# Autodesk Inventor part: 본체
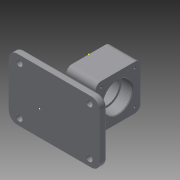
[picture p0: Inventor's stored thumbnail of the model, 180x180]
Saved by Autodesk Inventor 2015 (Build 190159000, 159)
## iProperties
Created: 2020-11
Part Number: 본체
Material: 일반
Document SubType Name: Modeling
Designer: pc-04
Density: 1 g/cm^3
Appearance: 기본값
Author: pc-04
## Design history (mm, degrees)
sketch "스케치2"
  geometry: L1 (-32, 32)-(32, 32); L2 (32, 32)-(32, -32); L3 (32, -32)-(-32, -32); L4 (-32, -32)-(-32, 32); L5 (0, 7.175)-(0, -7.867) reference; L6 (9.729, 0)-(-7.281, 0) reference; 1 further point
  constraints: 12 end point, 3 horizontal, 2 parallel, 2 vertical, 1 perpendicular, 3 other
  dimensions: "d0" = 64 distance of L1.end L2.end; "d1" = 64 distance of L2.end L3.end; "d2" = 32 distance between parallel lines of L3 L6; "d3" = 32 distance between parallel lines of L4 L5
extrude "돌출1" new body sketch "스케치2" distance "d4" = 42; taper "d5" = 0 deg
sketch "스케치5"
  geometry: 1 further point
sketch "스케치6"
  geometry: C1 r 21 at (0, 0); 1 further point
  constraints: 1 centre point, 1 coincident
  dimensions: "d17" = 42 diameter of C1
extrude "돌출3" cut sketch "스케치6" distance "d18" = 16; taper "d19" = 0 deg
sketch "스케치7"
  geometry: C1 r 21 at (0, 0); 1 further point
  constraints: 1 centre point, 1 coincident
  dimensions: "d20" = 42 diameter of C1
extrude "돌출4" cut sketch "스케치7" distance "d21" = 16; taper "d22" = 0 deg
sketch "스케치8"
  geometry: 1 further point
sketch "스케치9"
  geometry: C1 r 18 at (0, 0); 1 further point
  constraints: 1 centre point, 1 coincident
  dimensions: "d23" = 36 diameter of C1
extrude "돌출5" cut sketch "스케치9" distance "d24" = 16; taper "d25" = 0 deg
sketch "스케치10"
  geometry: 4 further points
hole "구멍1" sketch "스케치10" at (-24, 24), (-24, -24), (24, -24), (24, 24) diameter "d31" = 3.242; stored, may be unused: countersink angle "d35" = 90 deg, drill point angle "d37" = 118 deg; dims "d32" = 8, "d33" = 4, "d34" = 2, "d36" = 10
sketch "스케치11"
  geometry: L1 (0, 42.923)-(0, -48.07); L2 (-61.306, 0)-(57.445, 0); L3 (24, 42.923)-(24, -48.07); L4 (-24, 42.923)-(-24, -48.07); L5 (-61.306, 24)-(57.445, 24); L6 (-61.306, -24)-(57.445, -24); 5 further points
  constraints: 12 end point, 8 point on line, 4 parallel, 1 horizontal, 1 vertical
  dimensions: "d38" = 24 distance between parallel lines of L1 L3; "d39" = 24 distance between parallel lines of L1 L4; "d40" = 24 distance between parallel lines of L2 L5; "d41" = 24 distance between parallel lines of L2 L6
hole "구멍2" sketch "스케치11" at (-24, 24), (-24, -24), (24, -24), (24, 24) diameter "d42" = 3.242; stored, may be unused: countersink angle "d46" = 90 deg, drill point angle "d48" = 118 deg; dims "d43" = 8, "d44" = 4, "d45" = 2, "d47" = 10
node "작업 평면2"
sketch "스케치14"
  geometry: 1 further point
sketch "스케치15"
  geometry: 1 further point
sketch "스케치16" dims "d24" = 16
  geometry: L1 (-42, -32)-(0, -32); L2 (44, 52)-(-86, 52); L3 (-86, 52)-(-86, -36); L4 (-86, -36)-(44, -36); L5 (44, -36)-(44, 52); L6 (0, -33.785)-(0, 34.387); L7 (0, 32)-(0, -32) reference; L8 (-21, -33.785)-(-21, 34.387)
  constraints: 14 end point, 3 parallel, 1 collinear, 1 horizontal, 1 perpendicular, 1 other
  dimensions: "d78" = 130 distance of L2.start L2.end; "d79" = 88 distance of L2.end L3.end; "d201" = 21 distance between parallel lines of L6 L8; "d202" = 65 distance between parallel lines of L5 L8
extrude "돌출8" join sketch "스케치16" distance "d84" = 10; taper "d85" = 0 deg
sketch "스케치19"
  geometry: L1 (0, -32)-(42, -32); L2 (42, 32)-(0, 32); L3 (47.791, -32)-(-18.485, -32); L4 (86, 36)-(-44, 36) reference; L5 (0, 32)-(0, -4); L6 (0, -20)-(0, -32); L7 (4, -20)-(4, -39.483); L8 (4, -20)-(-18.485, -20); L9 (17, -32)-(17, -39.483); L10 (21, -32)-(21, -39.483); L11 (25, -32)-(25, -39.483); L12 (47.791, -20)-(38, -20); L13 (25, -20)-(17, -20); L14 (38, -20)-(38, -39.483); L15 (42, -20)-(42, -39.483); L16 (42, -32)-(42, -20); L17 (42, -4)-(42, 0); L18 (42, 4)-(42, 32); L19 (42, 36)-(42, 4); L20 (42, 0)-(42, -4); L21 (47.791, 4)-(42, 4); L22 (38, 36)-(38, 20); L23 (38, 4)-(38, -4); L24 (47.791, 20)-(38, 20); L25 (25, 36)-(25, 32); L26 (21, 36)-(21, 32); L27 (17, 36)-(17, 32); L28 (25, 20)-(17, 20); L29 (4, 20)-(-18.485, 20); L30 (4, 36)-(4, 20); L31 (4, 4)-(4, -4); L32 (0, 4)-(-18.485, 4); L33 (0, 0)-(-18.485, 0); L34 (0, -4)-(-18.485, -4); L35 (17, 20)-(17, 4); L36 (17, -4)-(17, -20); L37 (25, 20)-(25, 4); L38 (25, -4)-(25, -20); L39 (38, -4)-(25, -4); L40 (17, -4)-(4, -4); L41 (38, 4)-(25, 4); L42 (17, 4)-(4, 4)
  constraints: 82 end point, 55 parallel, 11 point on line, 3 perpendicular, 2 horizontal, 1 midpoint
extrude "돌출11" join sketch "스케치19" distance "d159" = 30; taper "d160" = 0 deg
fillet "모깎기1" dims "d172" = 8
sketch "스케치20"
  geometry: L1 (-39, -54.344)-(-39, 46.653); L2 (-41.097, -52)-(84.907, -52); L3 (-44, -52)-(86, -52) reference; L4 (-29, -54.344)-(-29, 46.653); L5 (71, -54.344)-(71, 46.653); L6 (-41.097, -42)-(84.907, -42); L7 (-41.097, 26)-(84.907, 26); 5 further points
  constraints: 12 end point, 8 point on line, 4 parallel, 1 collinear, 1 vertical
  dimensions: "d173" = 10 distance between parallel lines of L1 L4; "d174" = 110 distance between parallel lines of L1 L5; "d175" = 10 distance between parallel lines of L2 L6; "d176" = 78 distance between parallel lines of L2 L7
hole "구멍3" sketch "스케치20" at (71, -42), (71, 26), (-29, -42), (-29, 26) diameter "d177" = 9; stored, may be unused: countersink angle "d181" = 90 deg, drill point angle "d183" = 118 deg; dims "d178" = 8, "d179" = 4, "d180" = 2, "d182" = 10
fillet "모깎기2" dims "d184" = 12
fillet "모깎기3" dims "d185" = 12
chamfer "모따기1" distance "d186" = 1; stored, may be unused: second distance "d187" = 2, angle "d188" = 45 deg
fillet "모깎기4" dims "d189" = 0.3
chamfer "모따기2" distance "d190" = 1; stored, may be unused: second distance "d191" = 2, angle "d192" = 45 deg
fillet "모깎기5" dims "d193" = 3
fillet "모깎기6" dims "d194" = 3
fillet "모깎기7" dims "d195" = 3
fillet "모깎기8" dims "d196" = 3
sketch "스케치21"
  geometry: L1 (0, 32)-(42, 32); L2 (42, 32)-(42, -32); L3 (42, -32)-(0, -32); L4 (0, -32)-(0, 32); L5 (-7.399, 32)-(51.311, 32); L6 (-7.399, 0)-(51.311, 0); L7 (-32, -52)-(74, -52) reference; L8 (-44, 24)-(-44, -40) reference; 2 further points
  constraints: 12 end point, 3 parallel, 2 horizontal, 1 perpendicular, 1 point on line, 1 other
  dimensions: "d197" = 32 distance between parallel lines of L5 L6; "d200" = 65 distance from line of L8 point (21, -42)
feature "엠보싱1" sketch "스케치21" dims "d0" = 64, "d1" = 64, "d2" = 32, "d3" = 32, "d203" = 0.5, "d204" = 0
sketch "스케치22"
  geometry: 1 further point
node "솔리드1"
other parameters: "d64" = 62, "d65" = 65, "d66" = 4, "d67" = 4, "d68" = 4, "d69" = 4, "d74" = 17, "d75" = 17, "d87" = 44, "d88" = 4, "d89" = 4, "d90" = 4, "d91" = 4, "d92" = 17, "d93" = 17, "d101" = 65, "d102" = 52, "d104" = 4, "d105" = 4, "d106" = 4, "d107" = 4, "d108" = 17, "d109" = 17, "d112" = 55, "d113" = 62, "d114" = 4, "d115" = 4, "d116" = 4, "d117" = 4, "d118" = 4, "d119" = 17, "d120" = 17, "d125" = 65, "d126" = 4, "d127" = 4, "d128" = 4, "d129" = 4, "d130" = 17, "d131" = 17, "d148" = 62, "d151" = 4, "d152" = 4, "d153" = 4, "d154" = 4, "d155" = 17, "d156" = 17, "d162" = 32, "d163" = 21, "d164" = 4, "d165" = 4, "d166" = 4, "d167" = 4, "d168" = 17, "d169" = 17
